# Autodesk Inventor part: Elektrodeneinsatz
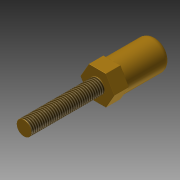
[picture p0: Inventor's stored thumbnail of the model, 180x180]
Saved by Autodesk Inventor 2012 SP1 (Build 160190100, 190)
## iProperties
Created: 2012-10
Part Number: Elektrodeneinsatz
Material: Default
Document SubType Name: Modeling
Designer: Dominic Mähling
Density: 1 g/cm^3
Author: Dominic Mähling
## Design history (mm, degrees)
derived "Funkenstrecke master.ipt"
feature "Elektrodeneinsatz::Funkenstrecke master.ipt" dims "d0" = 10
tag "Bezeichnung1"
node "Volumenkörper1"
